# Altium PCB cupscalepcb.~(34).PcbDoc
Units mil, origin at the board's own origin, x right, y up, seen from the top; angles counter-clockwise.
Board outline 3600 x 4600 mil, 2 copper layers (Top Layer, Bottom Layer); 10 components, 8 nets, 35 pads, 0 vias.
Unrouted connection lines stored in the file: 1.
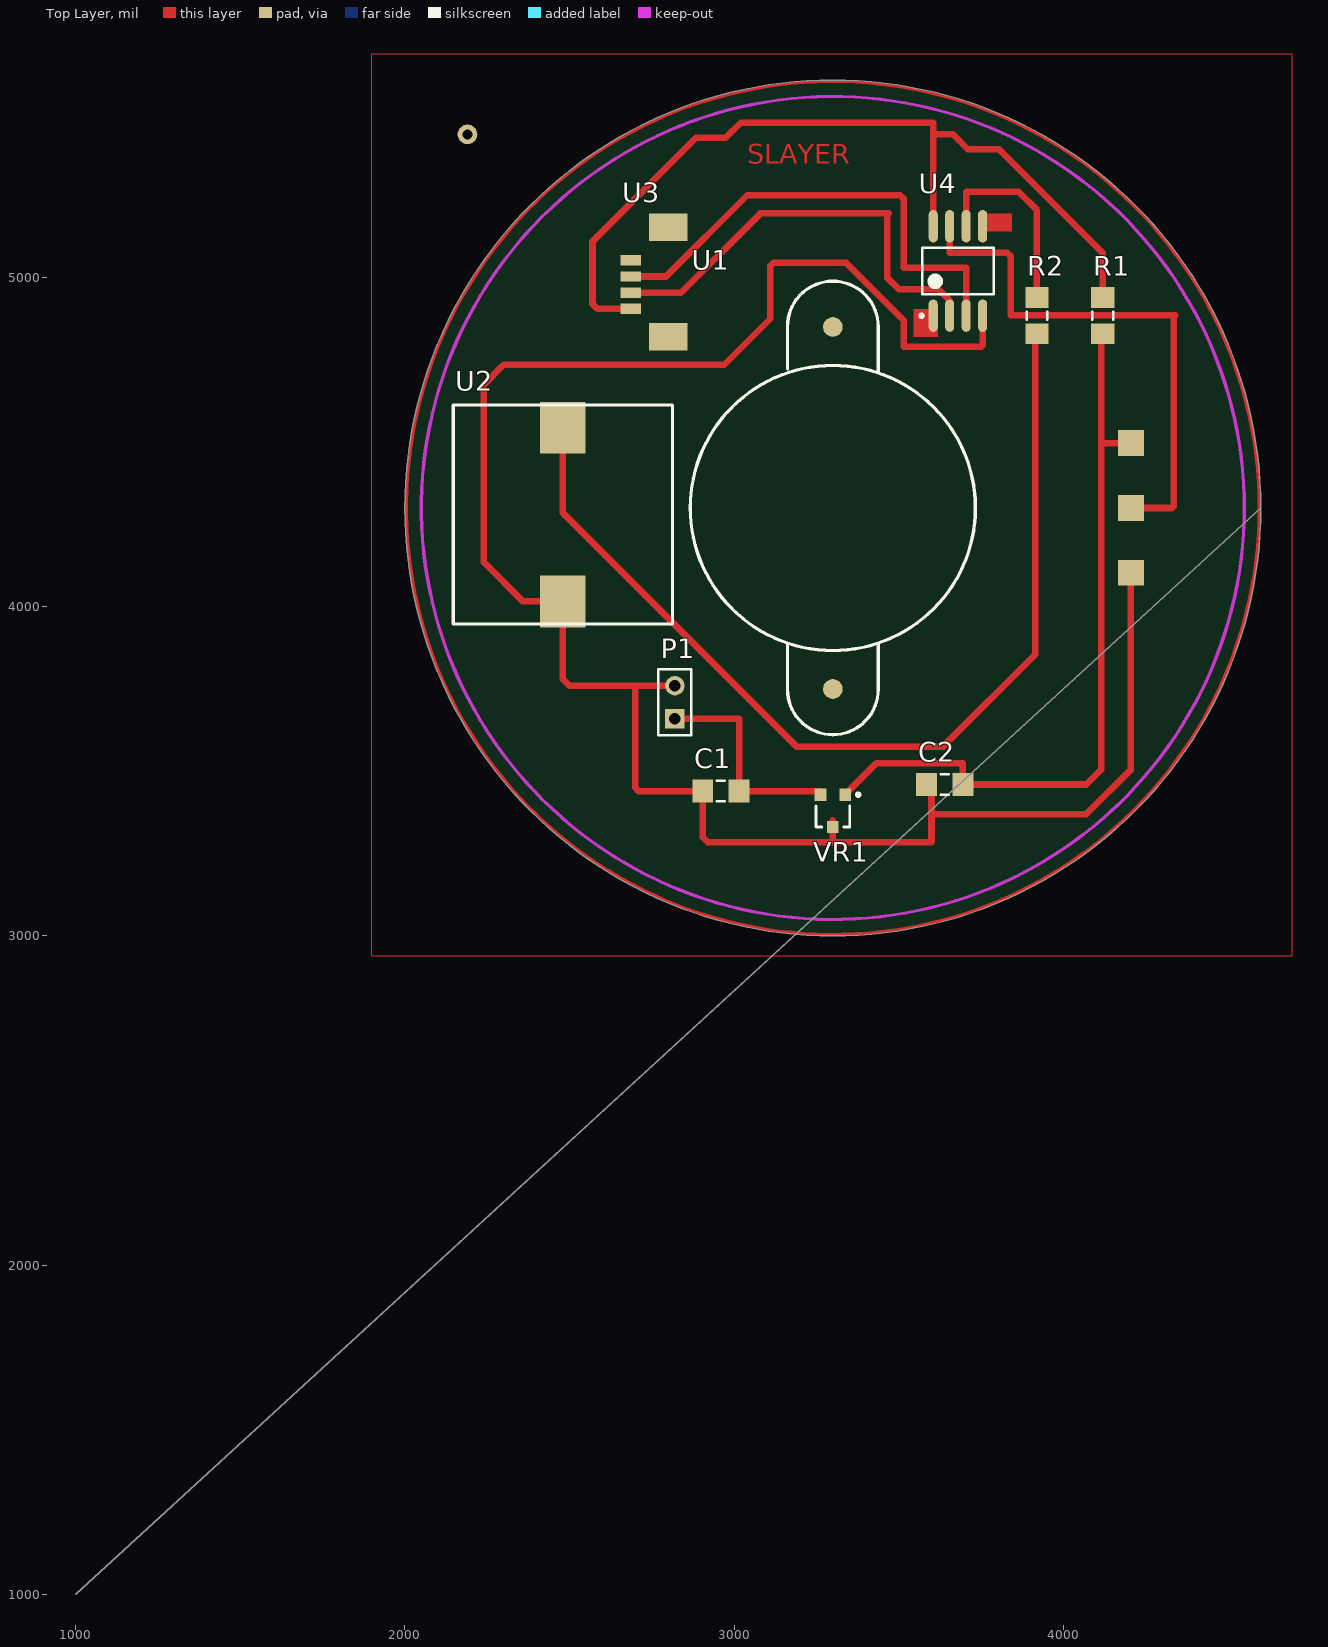
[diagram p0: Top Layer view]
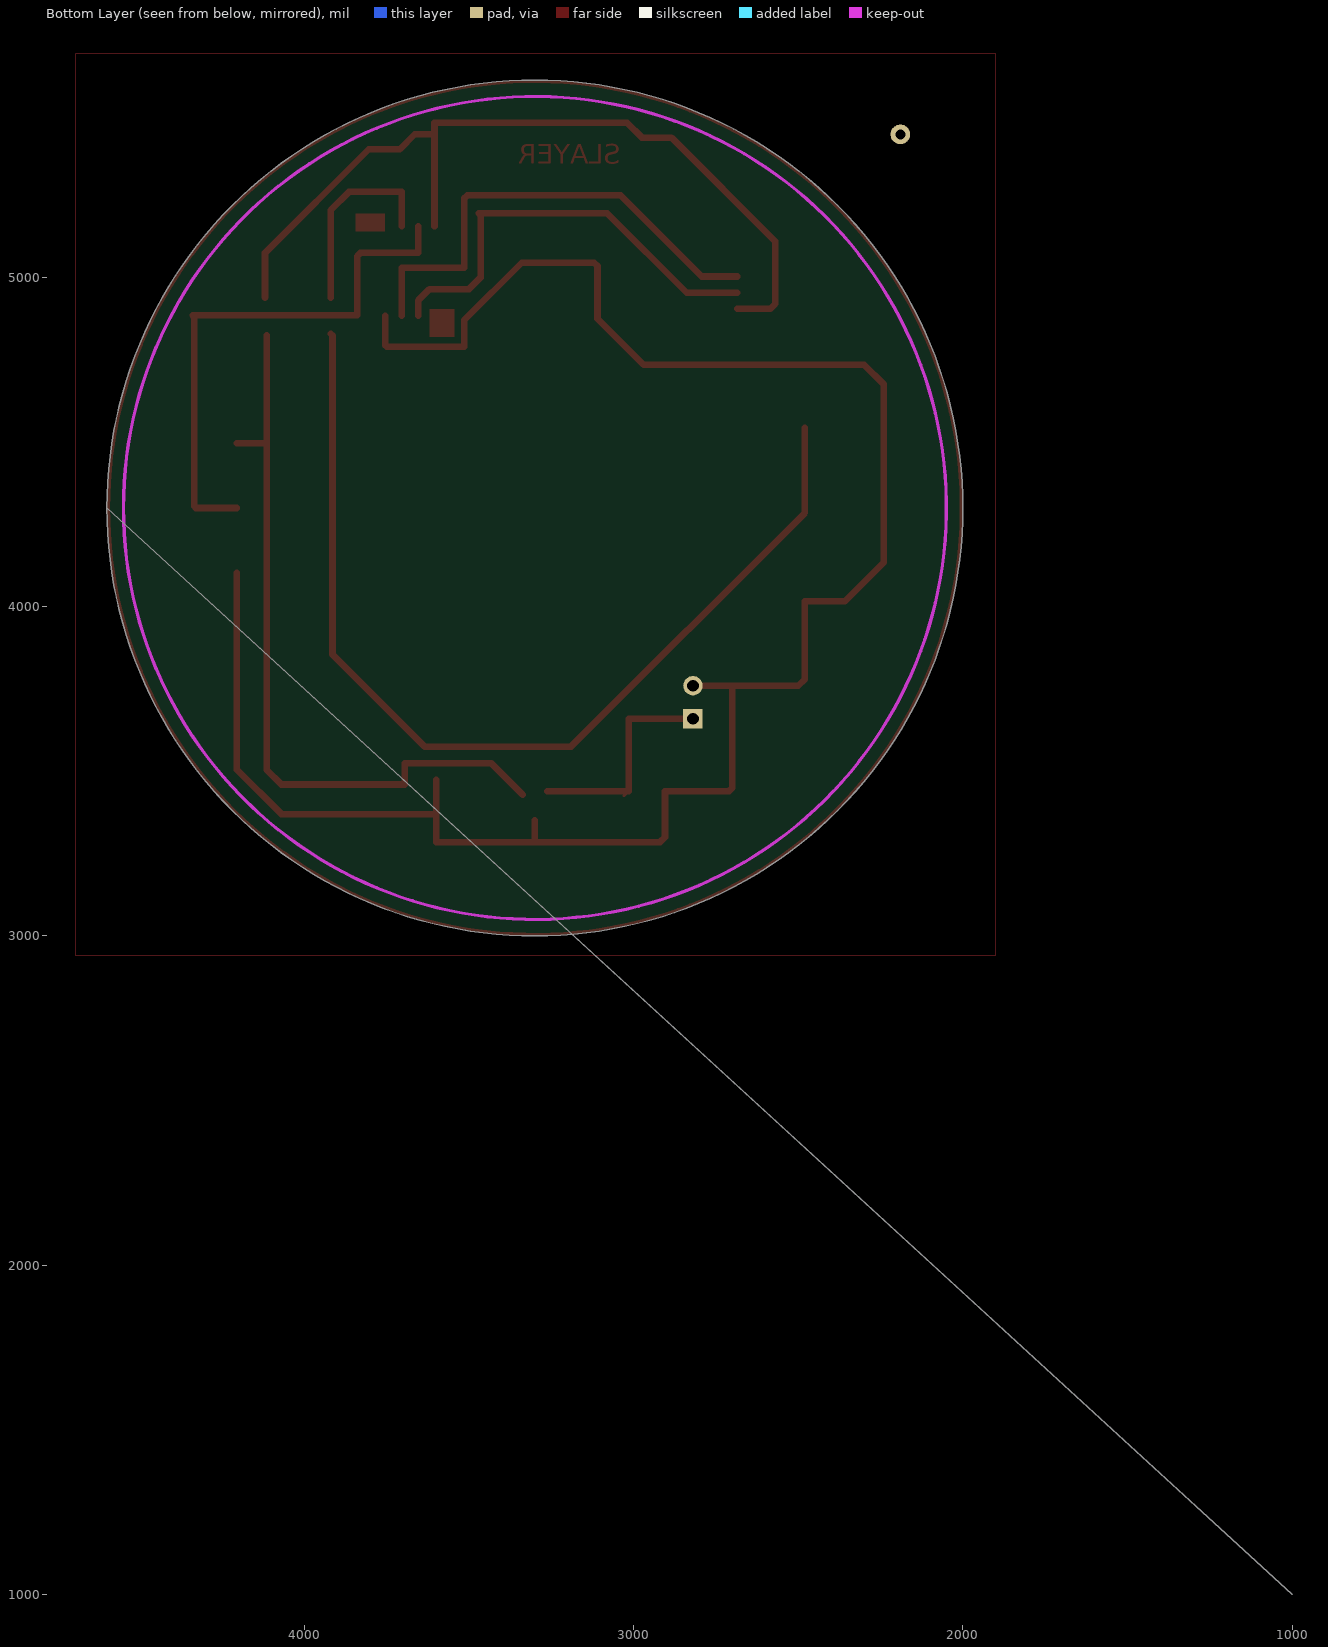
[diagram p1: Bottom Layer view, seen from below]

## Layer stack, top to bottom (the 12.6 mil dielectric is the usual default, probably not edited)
Top Layer: signal copper 1.4
Dielectric: dielectric 12.6, FR-4, Dk 4.8
Bottom Layer: signal copper 1.4

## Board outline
4600,4300 ccw(c3300,4300) 3300,5600 ccw(c3300,4300) 2000,4300 ccw(c3300,4300) 3300,3000 ccw(c3300,4300) 1000,1000

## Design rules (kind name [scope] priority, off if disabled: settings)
Clearance [All] p1: gap=16
ComponentClearance [All] p1: gap=10 collisioncheckmode=2 verticalgap=10
PolygonConnect [All] p1: connectstyle=Relief reliefconductorwidth=10 reliefentries=4 polygonreliefangle="90 Angle"
RoutingVias [All] p1: holewidth=25 width=40 viastyle="Through Hole" minholewidth=28 minwidth=50 maxholewidth=28 maxwidth=50
SolderMaskExpansion [All] p1: expansion=4
TestPointUsage [All] p1: valid=0 allowmultiple=FALSE
Testpoint [All] p1: side=15 testpointundercomponent=TRUE minsize=40 maxsize=100 preferedsize=60 minholesize=0 maxholesize=40 preferedholesize=32 testpointgrid=1 style=1023 order=0123456789
Width [All] p1: maxlimit=22 minlimit=15 preferedwidth=20
18 further rules are at their usual default settings.

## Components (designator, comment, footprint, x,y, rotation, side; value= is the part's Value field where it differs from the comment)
C1 "Cap" 3216[1206] 2960,3440 r0 top
C2 "Cap" 3216[1206] 3640,3460 r0 top
P1 "Header 2" HDR1X2 2820,3660 r90 top
R1 "Res1" 3216[1206] 4120,4884.17 r90 top
R2 "Res1" 3216[1206] 3920,4884.17 r270 top
U1 "FC21" "FC21-Load Cell" 3300,4300 r0 top locked
U2 "CM-1240" CMI-1240-buzzer 2480,4280 r0 top
U3 "Molex Connector" "4 PIN Molex" 2800,4820 r90 top
U4 "ATtiny45" 8S2_M 3680,5020 r90 top
VR1 "Volt Reg" SOT-23 3300,3380 r180 top

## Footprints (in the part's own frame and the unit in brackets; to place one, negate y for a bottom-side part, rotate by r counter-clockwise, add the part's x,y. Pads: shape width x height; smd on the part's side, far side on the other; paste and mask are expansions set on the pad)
"4 PIN Molex" [mm]
  rect 0.8x1.6 smd: 0(2.15,2.9) 1(3.4,2.9) 2(4.65,2.9) 3(5.9,2.9)
  rect 2.1x3 smd: 8(0,0) 15(8.45,0)
8S2_M [mm] "SOP, 8-Leads, Body 5.3x5.3mm, Pitch 1.27mm, IPC Low Density"
  oval 2.5x0.7 smd: 1(-3.45,1.905) 2(-3.45,0.635) 3(-3.45,-0.635) 4(-3.45,-1.905) 5(3.45,-1.905) 6(3.45,-0.635) 7(3.45,0.635) 8(3.45,1.905)
  silkscreen extent -3.57,-2.75 1.8,2.93, body extent -2.73,-2.75 2.73,2.75, height 2.03
3216[1206] [mm] "Chip Resistor; Body 3.2 x 1.6 mm (LxW typ)"
  rect 1.6x1.8 smd: 1(-1.4,0) 2(1.4,0)
  silkscreen extent -0.3,-0.8 0.3,0.8
CMI-1240-buzzer [mm]
  rect 3.5x4 smd: 0(0,6.7) 1(0,-6.7)
  silkscreen extent -8.45,-8.45 8.45,8.45
"FC21-Load Cell" [mm]
  round 1.524 smd: 0(0,13.97) 1(0,-13.97)
  rect 2x2 smd: 0(23,5) 1(23,0) 2(23,-5)
  silkscreen extent -11,-17.5 11,17.5
HDR1X2 [mm] "Connector; Header; 2 Position"
  rect 1.5x1.5 hole 0.9: 1(0,0)
  round 1.5 hole 0.9: 2(2.54,0)
  silkscreen extent -1.27,-1.27 3.81,1.27
SOT-23 [mm] "SOT-23; 3 Leads; Body 3.0 x 2.6 mm, inc. leads (LxW max)"
  rect 0.9x0.95 smd: 1(-0.95,-1.25) 2(0.95,-1.25) 3(0,1.25)
  silkscreen extent -2.08,-1.37 1.3,1.25

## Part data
C1 C2: "Capacitor"
P1: "Header, 2-Pin"
R1 R2: "Resistor"
U2: library part CMI-1240
U4: "8-Bit AVR Microcontroller with 1K Byte of Flash Memory"
VR1: "Voltage Regulator"

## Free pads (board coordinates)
  round 60 hole 30: 0(2190,5435)

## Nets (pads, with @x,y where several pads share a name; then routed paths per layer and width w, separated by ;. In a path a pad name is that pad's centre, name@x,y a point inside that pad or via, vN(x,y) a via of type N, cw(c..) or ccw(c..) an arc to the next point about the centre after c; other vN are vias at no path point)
GND: C1.1 C2.1 P1.2 U1.2 U2.1 U4.4 VR1.3 | length 6294.8
  Top Layer w20: 2700,3760 2700,3450 2710,3440 C1.1 2904.88,3299.88 2919.76,3285 3599.76,3285 C2.1@3599.76,3474.88 ; P1.2 2500,3760 2480,3780 U2.1 2358.78,4016.22 2240,4135 2240,4675 2300,4735 2970,4735 3110,4875 3110,5035 3120,5045 3340,5045 3515,4870 3515,4790 3750,4790 3755,4795 U4.4 ; 3300,3285 3300,3350.79 ; 3599.76,3370 4070,3370 4205.51,3505.51 U1.2
NetC1_2: C1.2 P1.1 VR1.2 | length 682.7
  Top Layer w8: 3015,3660 3015.12,3659.88 ; C1.2 C1.2@3029.37,3425.75
  Top Layer w20: P1.1 3015,3660 ; 3015.12,3659.88 C1.2 VR1.2@3262.6,3440
NetC2_2: C2.2 R1.1 R1.2 U1.0@4205.51,4496.85 U3.0 U4.8 VR1.1 | length 4912.3
  Top Layer w20: U3.0 2585.35,4904.65 2570,4920 2570,5109.63 2885.37,5425 2975,5425 3020,5470 3605,5470 U4.8 ; VR1.1 3433.07,3524.88 3695.12,3524.88 C2.2 4070,3460 4115,3505 R1.1@4115,4824.06 ; 3605,5435 3665,5435 3710,5390 3805,5390 4120,5075 R1.2 ; 4123.15,4496.85 U1.0@4205.51,4496.85
NetR2_1: R2.1 U4.6 | length 607.7
  Top Layer w20: U4.6 3705,5260 3865,5260 3920,5205 R2.1
NetR2_2: R2.2 U2.0 | length 3080
  Top Layer w20: U2.0 2480,4285 3190,3575 3635,3575 3915,3855 3915,4824.06 R2.2
NetU1_1: U1.1@4205.51,4300 U4.7 | length 1663.6
  Top Layer w20: U4.7 3655,5075 3830,5075 3840,5065 3840,4885 4340,4885 4335,4880 4335,4305 4330,4300 U1.1@4205.51,4300
NetU3_1: U3.1 U4.2 | length 1346
  Top Layer w20: U3.1 2838.86,4953.86 3080,5195 3470,5195 3465,5190 3465,5000 3500,4965 3620,4965 3655,4930 U4.2
NetU3_2: U3.2 U4.3 | length 1481.4
  Top Layer w20: U3.2 2793.07,5003.07 3040,5250 3505,5250 3515,5240 3515,5030 3705,5030 U4.3
pads on no net: U1.0@3300,4850 U1.1@3300,3750 U3.3 U3.8 U3.15 U4.1 U4.5
copper on no net: | length 19210.2
  Top Layer w0: 1900,2940 1900,5655 1900,5680 4695,5680 4695,2940 1900,2940
  Top Layer w10: 4595.55,4300 ccw(c3300,4300) 4595.55,4300

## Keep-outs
Keep-Out Layer:
  circle w10: c3300,4300 r1250

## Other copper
Top Layer:
  rectangle: 3545,4820 3620,4905
  rectangle: 3755,5140 3845,5195
  text "SLAYER" at 3040,5345 h60

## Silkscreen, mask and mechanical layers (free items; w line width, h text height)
Drill Drawing:
  text ".LEGEND" at 4800,3200 h60
  text "Drill Drawing." at 4800,3100 h60

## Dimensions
4550,4300 to 2050,4300 on Mechanical 1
